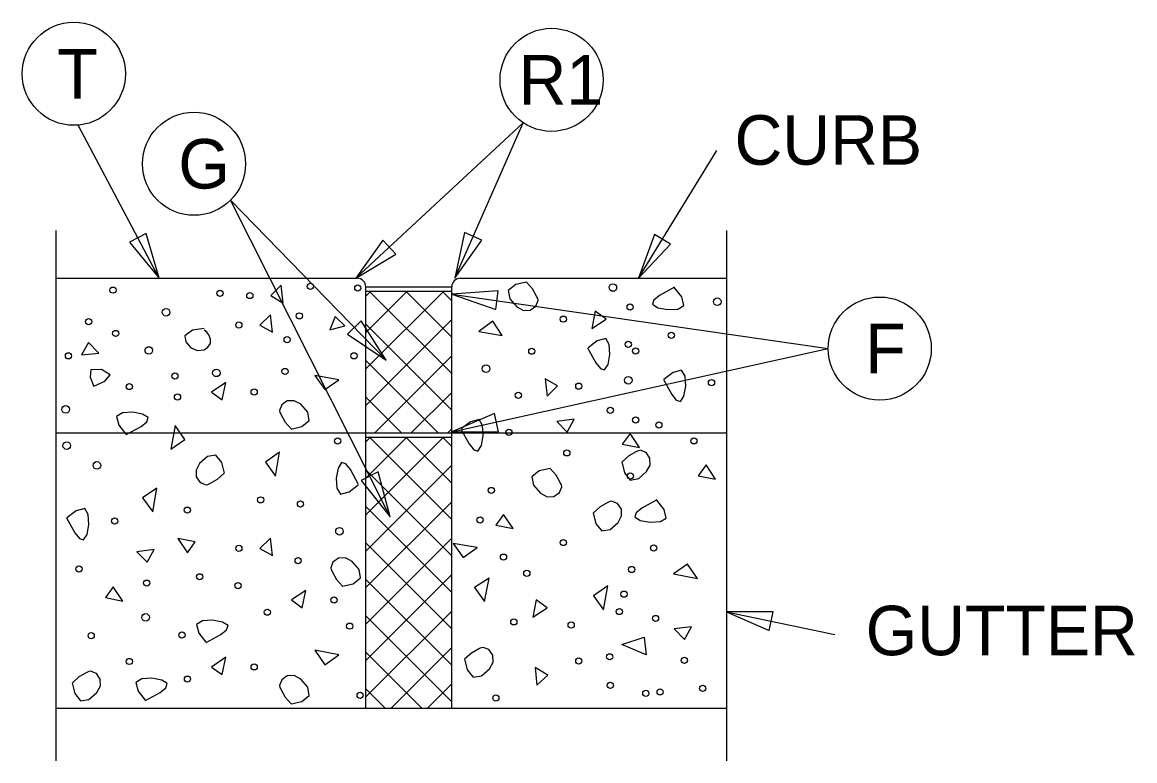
# Model space of a CAD drawing. Extents: x -439.1 to -407.9, y -458.1 to -436.2.
# Drawn here: x -431.656 to -428.285, y -452.451 to -450.213 of the extents above; entities that cross this region are included whole.
import ezdxf

# ---------------------------------------------------------------- set-up
doc = ezdxf.new("R2010")
doc.units = 0
doc.layers.add('Level 4', color=7, linetype='Continuous')

msp = doc.modelspace()

# ---------------------------------------------------------------- linework, layer by layer
at = {"layer": 'Level 4'}
for p, q in [((-431.2411, -450.9886), (-431.4866, -450.5246)), ((-430.645, -450.9886), (-430.1384, -450.5173)), ((-430.3448, -450.9886), (-430.1384, -450.5173)), ((-429.7884, -450.9886), (-429.5514, -450.6016)), ((-430.5533, -451.237), (-431.0251, -450.7522)), ((-430.5408, -451.7122), (-431.0251, -450.7522)), ((-431.5528, -452.4511), (-431.5528, -450.8438)), ((-429.5215, -452.4511), (-429.5215, -450.8438)), ((-431.5528, -450.9887), (-430.6415, -450.9887)), ((-430.329, -450.9887), (-429.5215, -450.9887)), ((-430.8715, -451.0099), (-430.9028, -451.0412)), ((-430.9028, -451.0412), (-430.8653, -451.0637)), ((-430.8653, -451.0637), (-430.8715, -451.0099)), ((-430.6153, -452.2912), (-430.6153, -451.0149)), ((-430.6153, -451.0149), (-430.354, -451.0149)), ((-430.6153, -451.0274), (-430.354, -451.0274)), ((-430.6149, -451.2635), (-430.3791, -451.0276)), ((-430.6149, -451.153), (-430.4896, -451.0276)), ((-430.6149, -451.0425), (-430.6, -451.0276)), ((-430.3545, -451.2778), (-430.6047, -451.0276)), ((-430.3545, -451.1673), (-430.4942, -451.0276)), ((-430.3545, -451.0569), (-430.3838, -451.0276)), ((-430.3545, -451.0369), (-429.2142, -451.2016)), ((-430.354, -452.2912), (-430.354, -451.0149)), ((-430.904, -451.0999), (-430.9365, -451.1312)), ((-430.8978, -451.1524), (-430.904, -451.0999)), ((-430.7078, -451.1049), (-430.724, -451.1449)), ((-430.679, -451.1324), (-430.7078, -451.1049)), ((-429.9203, -451.0887), (-429.9303, -451.1412)), ((-429.8865, -451.1124), (-429.9203, -451.0887)), ((-430.9365, -451.1312), (-430.8978, -451.1524)), ((-430.724, -451.1449), (-430.679, -451.1324)), ((-430.6149, -451.3739), (-430.3545, -451.1135)), ((-430.3545, -451.3883), (-430.6149, -451.1279)), ((-430.2303, -451.1187), (-430.2728, -451.1499)), ((-430.2015, -451.1624), (-430.2303, -451.1187)), ((-429.9303, -451.1412), (-429.8865, -451.1124)), ((-430.2728, -451.1499), (-430.2015, -451.1624)), ((-431.4553, -451.1837), (-431.4765, -451.2212)), ((-431.424, -451.2162), (-431.4553, -451.1837)), ((-430.3545, -451.4538), (-429.2142, -451.2016)), ((-431.4765, -451.2212), (-431.424, -451.2162)), ((-430.396, -451.4573), (-430.6149, -451.2384)), ((-430.5878, -451.4573), (-430.3545, -451.224)), ((-431.039, -451.3049), (-431.0828, -451.3337)), ((-431.0503, -451.3574), (-431.039, -451.3049)), ((-430.6965, -451.2962), (-430.769, -451.2837)), ((-430.769, -451.2837), (-430.739, -451.3262)), ((-430.739, -451.3262), (-430.6965, -451.2962)), ((-430.0715, -451.2937), (-430.0653, -451.3462)), ((-430.034, -451.3149), (-430.0715, -451.2937)), ((-431.0828, -451.3337), (-431.0503, -451.3574)), ((-430.4773, -451.4573), (-430.3545, -451.3345)), ((-430.0653, -451.3462), (-430.034, -451.3149)), ((-430.5065, -451.4573), (-430.6149, -451.3489)), ((-431.1928, -451.4349), (-431.2053, -451.5062)), ((-431.1628, -451.4774), (-431.1928, -451.4349)), ((-430.3668, -451.4573), (-430.3545, -451.445)), ((-429.984, -451.4162), (-430.0365, -451.4224)), ((-430.0365, -451.4224), (-430.0053, -451.4549)), ((-430.0053, -451.4549), (-429.984, -451.4162)), ((-431.5528, -451.4574), (-429.5215, -451.4574)), ((-431.2053, -451.5062), (-431.1628, -451.4774)), ((-430.6153, -451.4699), (-430.354, -451.4699)), ((-430.6149, -451.7054), (-430.3799, -451.4703)), ((-430.6149, -451.5949), (-430.4903, -451.4703)), ((-430.6149, -451.4844), (-430.6008, -451.4703)), ((-430.3545, -451.7198), (-430.604, -451.4703)), ((-430.3545, -451.6093), (-430.4935, -451.4703)), ((-430.3545, -451.4988), (-430.383, -451.4703)), ((-429.814, -451.4587), (-429.8378, -451.4912)), ((-429.7853, -451.5012), (-429.814, -451.4587)), ((-429.8378, -451.4912), (-429.7853, -451.5012)), ((-430.8765, -451.5162), (-430.919, -451.5462)), ((-430.919, -451.5462), (-430.889, -451.5887)), ((-430.889, -451.5887), (-430.8765, -451.5162)), ((-430.6149, -451.8159), (-430.3545, -451.5555)), ((-430.3545, -451.8302), (-430.6149, -451.5698)), ((-429.584, -451.5537), (-429.6078, -451.5874)), ((-429.5553, -451.5974), (-429.584, -451.5537)), ((-429.6078, -451.5874), (-429.5553, -451.5974)), ((-431.2478, -451.6249), (-431.2915, -451.6537)), ((-431.2603, -451.6962), (-431.2478, -451.6249)), ((-431.2915, -451.6537), (-431.2603, -451.6962)), ((-430.6149, -451.9263), (-430.3545, -451.6659)), ((-430.3545, -451.9407), (-430.6149, -451.6803)), ((-430.1978, -451.7049), (-430.2215, -451.7374)), ((-430.169, -451.7474), (-430.1978, -451.7049)), ((-430.2215, -451.7374), (-430.169, -451.7474)), ((-431.184, -451.7774), (-431.1553, -451.8212)), ((-431.1315, -451.7874), (-431.184, -451.7774)), ((-430.904, -451.7762), (-430.9365, -451.8074)), ((-430.8978, -451.8287), (-430.904, -451.7762)), ((-430.6149, -452.0368), (-430.3545, -451.7764)), ((-431.2565, -451.8112), (-431.309, -451.8174)), ((-431.2778, -451.8487), (-431.2565, -451.8112)), ((-431.1553, -451.8212), (-431.1315, -451.7874)), ((-430.9365, -451.8074), (-430.8978, -451.8287)), ((-430.3545, -452.0512), (-430.6149, -451.7908)), ((-430.2778, -451.8049), (-430.3503, -451.7924)), ((-430.3503, -451.7924), (-430.3203, -451.8349)), ((-430.3203, -451.8349), (-430.2778, -451.8049)), ((-431.309, -451.8174), (-431.2778, -451.8487)), ((-429.6403, -451.8549), (-429.6828, -451.8849)), ((-429.6103, -451.8987), (-429.6403, -451.8549)), ((-430.6149, -452.1473), (-430.3545, -451.8869)), ((-430.3545, -452.1617), (-430.6149, -451.9013)), ((-430.2415, -451.8974), (-430.2853, -451.9262)), ((-430.2553, -451.9687), (-430.2415, -451.8974)), ((-429.6828, -451.8849), (-429.6103, -451.8987)), ((-431.3803, -451.9237), (-431.404, -451.9562)), ((-431.3515, -451.9674), (-431.3803, -451.9237)), ((-430.7965, -451.9349), (-430.8403, -451.9637)), ((-430.8078, -451.9874), (-430.7965, -451.9349)), ((-430.2853, -451.9262), (-430.2553, -451.9687)), ((-429.8815, -451.9212), (-429.9253, -451.9512)), ((-429.9253, -451.9512), (-429.8953, -451.9937)), ((-429.8953, -451.9937), (-429.8815, -451.9212)), ((-431.404, -451.9562), (-431.3515, -451.9674)), ((-430.8403, -451.9637), (-430.8078, -451.9874)), ((-430.099, -451.9637), (-430.109, -452.0162)), ((-430.0653, -451.9874), (-430.099, -451.9637)), ((-430.6149, -452.2578), (-430.3545, -451.9974)), ((-430.3545, -452.2722), (-430.6149, -452.0118)), ((-430.109, -452.0162), (-430.0653, -451.9874)), ((-429.522, -451.9999), (-429.1939, -452.0688)), ((-429.6278, -452.0449), (-429.6803, -452.0512)), ((-429.6803, -452.0512), (-429.649, -452.0837)), ((-429.649, -452.0837), (-429.6278, -452.0449)), ((-429.839, -452.0987), (-429.7715, -452.0762)), ((-429.7715, -452.0762), (-429.7653, -452.1299)), ((-430.6965, -452.1299), (-430.769, -452.1162)), ((-430.769, -452.1162), (-430.739, -452.1599)), ((-430.5372, -452.2906), (-430.3545, -452.1079)), ((-429.7653, -452.1299), (-429.839, -452.0987)), ((-431.039, -452.1374), (-431.0828, -452.1674)), ((-431.0503, -452.1899), (-431.039, -452.1374)), ((-430.739, -452.1599), (-430.6965, -452.1299)), ((-430.4466, -452.2906), (-430.6149, -452.1222)), ((-431.0828, -452.1674), (-431.0503, -452.1899)), ((-430.1015, -452.1687), (-430.0965, -452.2224)), ((-430.064, -452.1912), (-430.1015, -452.1687)), ((-430.4268, -452.2906), (-430.3545, -452.2183)), ((-430.0965, -452.2224), (-430.064, -452.1912)), ((-430.557, -452.2906), (-430.6149, -452.2327)), ((-431.5528, -452.2912), (-429.5215, -452.2912))]:
    msp.add_line(p, q, dxfattribs=at)
for points in [[(-431.3312, -450.8797), (-431.2411, -450.9886), (-431.2804, -450.8529)], [(-430.3156, -450.8504), (-430.3448, -450.9886), (-430.263, -450.8734)], [(-429.7407, -450.8556), (-429.7884, -450.9886), (-429.6917, -450.8856)], [(-430.5633, -450.8733), (-430.645, -450.9886), (-430.5242, -450.9154)], [(-430.2136, -451.0265), (-430.3545, -451.0369), (-430.2212, -451.0835)], [(-430.6703, -451.1579), (-430.5533, -451.237), (-430.6292, -451.1178)], [(-430.2247, -451.3982), (-430.3545, -451.4538), (-430.2133, -451.4545)], [(-430.6287, -451.6017), (-430.5408, -451.7122), (-430.5774, -451.5758)], [(-429.3808, -452.0002), (-429.522, -451.9999), (-429.3926, -452.0564)]]:
    msp.add_lwpolyline(points, close=True, dxfattribs=at)
for points in [[(-430.128, -451.0003), (-430.1609, -451.008), (-430.1832, -451.026), (-430.1787, -451.0513), (-430.1575, -451.0756), (-430.1375, -451.0862), (-430.1167, -451.0856), (-430.0996, -451.0737), (-430.0928, -451.0561), (-430.0942, -451.0504), (-430.0966, -451.0448), (-430.1102, -451.021), (-430.128, -451.0009)], [(-429.68, -451.016), (-429.725, -451.041), (-429.7424, -451.0548), (-429.7465, -451.0674), (-429.7299, -451.0783), (-429.6997, -451.0837), (-429.6692, -451.0819), (-429.6511, -451.0712), (-429.658, -451.0451), (-429.6794, -451.0172)], [(-431.1045, -451.1405), (-431.1403, -451.1455), (-431.1635, -451.1631), (-431.1601, -451.1812), (-431.146, -451.1982), (-431.126, -451.2076), (-431.1052, -451.2058), (-431.0931, -451.198), (-431.0857, -451.1863), (-431.0855, -451.1729), (-431.0907, -451.16), (-431.0969, -451.1519), (-431.1045, -451.1455)], [(-429.9431, -451.1999), (-429.9181, -451.2449), (-429.9042, -451.2623), (-429.8916, -451.2665), (-429.8808, -451.2498), (-429.8754, -451.2197), (-429.8772, -451.1891), (-429.8879, -451.1711), (-429.914, -451.178), (-429.9418, -451.1993)], [(-431.4387, -451.3155), (-431.4056, -451.3005), (-431.3891, -451.2816), (-431.4155, -451.2648), (-431.4481, -451.2659), (-431.4499, -451.2888), (-431.4387, -451.3167)], [(-429.7133, -451.2958), (-429.6883, -451.3408), (-429.6744, -451.3582), (-429.6618, -451.3624), (-429.651, -451.3457), (-429.6456, -451.3156), (-429.6474, -451.285), (-429.6581, -451.267), (-429.6842, -451.2739), (-429.712, -451.2952)], [(-430.8415, -451.4456), (-430.8085, -451.4379), (-430.7862, -451.4199), (-430.7908, -451.3945), (-430.812, -451.3703), (-430.8319, -451.3597), (-430.8528, -451.3602), (-430.8698, -451.3721), (-430.8766, -451.3897), (-430.8753, -451.3954), (-430.8729, -451.401), (-430.8592, -451.4248), (-430.8415, -451.445)], [(-431.341, -451.4625), (-431.296, -451.4375), (-431.2787, -451.4237), (-431.2745, -451.4111), (-431.2911, -451.4002), (-431.3213, -451.3948), (-431.3519, -451.3966), (-431.3699, -451.4073), (-431.363, -451.4335), (-431.3416, -451.4613)], [(-430.3271, -451.446), (-430.3021, -451.491), (-430.2882, -451.5083), (-430.2756, -451.5125), (-430.2648, -451.4959), (-430.2594, -451.4657), (-430.2612, -451.4351), (-430.2719, -451.4171), (-430.298, -451.424), (-430.3258, -451.4454)], [(-429.8394, -451.5451), (-429.8317, -451.5781), (-429.8136, -451.6003), (-429.7883, -451.5958), (-429.7641, -451.5746), (-429.7534, -451.5547), (-429.754, -451.5338), (-429.7659, -451.5168), (-429.7835, -451.51), (-429.7892, -451.5113), (-429.7948, -451.5137), (-429.8186, -451.5273), (-429.8387, -451.5451)], [(-431.0433, -451.5797), (-431.051, -451.5467), (-431.069, -451.5245), (-431.0943, -451.529), (-431.1186, -451.5502), (-431.1292, -451.5701), (-431.1286, -451.591), (-431.1167, -451.608), (-431.0991, -451.6148), (-431.0934, -451.6135), (-431.0878, -451.6111), (-431.064, -451.5974), (-431.0439, -451.5797)], [(-430.6368, -451.6138), (-430.6618, -451.5688), (-430.6757, -451.5515), (-430.6883, -451.5473), (-430.6991, -451.5639), (-430.7045, -451.5941), (-430.7027, -451.6247), (-430.692, -451.6427), (-430.6659, -451.6358), (-430.6381, -451.6144)], [(-430.0564, -451.5649), (-430.0894, -451.5726), (-430.1116, -451.5906), (-430.1071, -451.6159), (-430.0859, -451.6402), (-430.066, -451.6508), (-430.0451, -451.6502), (-430.0281, -451.6383), (-430.0213, -451.6207), (-430.0226, -451.615), (-430.025, -451.6094), (-430.0387, -451.5856), (-430.0564, -451.5655)], [(-429.9262, -451.6995), (-429.9184, -451.7325), (-429.9004, -451.7547), (-429.8751, -451.7502), (-429.8509, -451.729), (-429.8402, -451.709), (-429.8408, -451.6882), (-429.8527, -451.6711), (-429.8703, -451.6643), (-429.876, -451.6657), (-429.8816, -451.6681), (-429.9054, -451.6817), (-429.9255, -451.6995)], [(-429.7334, -451.6604), (-429.7784, -451.6854), (-429.7958, -451.6992), (-429.7999, -451.7118), (-429.7833, -451.7227), (-429.7531, -451.7281), (-429.7225, -451.7263), (-429.7045, -451.7156), (-429.7115, -451.6895), (-429.7328, -451.6616)], [(-431.5217, -451.7151), (-431.4967, -451.7601), (-431.4828, -451.7775), (-431.4702, -451.7816), (-431.4594, -451.765), (-431.454, -451.7349), (-431.4558, -451.7043), (-431.4665, -451.6863), (-431.4926, -451.6932), (-431.5204, -451.7145)], [(-430.686, -451.9224), (-430.6531, -451.9147), (-430.6308, -451.8967), (-430.6353, -451.8714), (-430.6565, -451.8471), (-430.6765, -451.8365), (-430.6973, -451.8371), (-430.7144, -451.849), (-430.7212, -451.8666), (-430.7198, -451.8723), (-430.7174, -451.8779), (-430.7038, -451.9017), (-430.686, -451.9218)], [(-431.0989, -452.0931), (-431.054, -452.0681), (-431.0366, -452.0542), (-431.0324, -452.0416), (-431.0491, -452.0308), (-431.0792, -452.0254), (-431.1098, -452.0271), (-431.1278, -452.0378), (-431.1209, -452.064), (-431.0996, -452.0918)], [(-430.3155, -452.1426), (-430.3078, -452.1756), (-430.2897, -452.1978), (-430.2644, -452.1933), (-430.2402, -452.1721), (-430.2295, -452.1521), (-430.2301, -452.1313), (-430.242, -452.1142), (-430.2596, -452.1074), (-430.2653, -452.1088), (-430.2709, -452.1112), (-430.2947, -452.1248), (-430.3148, -452.1426)], [(-431.5047, -452.2147), (-431.497, -452.2476), (-431.479, -452.2699), (-431.4537, -452.2654), (-431.4294, -452.2442), (-431.4188, -452.2242), (-431.4194, -452.2034), (-431.4313, -452.1863), (-431.4489, -452.1795), (-431.4546, -452.1809), (-431.4602, -452.1833), (-431.484, -452.1969), (-431.5041, -452.2147)], [(-431.2829, -452.2688), (-431.2379, -452.2438), (-431.2205, -452.2299), (-431.2164, -452.2173), (-431.233, -452.2065), (-431.2632, -452.2011), (-431.2938, -452.2029), (-431.3118, -452.2136), (-431.3049, -452.2397), (-431.2835, -452.2675)], [(-430.8415, -452.2789), (-430.8085, -452.2712), (-430.7862, -452.2532), (-430.7908, -452.2278), (-430.812, -452.2036), (-430.8319, -452.193), (-430.8528, -452.1935), (-430.8698, -452.2054), (-430.8766, -452.223), (-430.8753, -452.2287), (-430.8729, -452.2343), (-430.8592, -452.2581), (-430.8415, -452.2783)]]:
    msp.add_lwpolyline(points, dxfattribs=at)
for centre, radius in [((-431.4996, -450.3689), 0.1562), ((-430.0521, -450.3872), 0.1562), ((-431.1355, -450.6417), 0.1562), ((-430.7832, -451.0134), 0.00937), ((-429.8665, -451.0167), 0.0115), ((-431.3809, -451.0247), 0.00937), ((-431.0565, -451.0346), 0.00937), ((-430.9664, -451.041), 0.00937), ((-430.6393, -451.0182), 0.00937), ((-429.8142, -451.0756), 0.00937), ((-429.5502, -451.0599), 0.0115), ((-429.0579, -451.2017), 0.1562), ((-431.2201, -451.0918), 0.0115), ((-430.8164, -451.1026), 0.00937), ((-430.0163, -451.1126), 0.00937), ((-431.4545, -451.1201), 0.00937), ((-430.9996, -451.1302), 0.00937), ((-431.3728, -451.156), 0.00937), ((-430.8533, -451.1749), 0.00937), ((-429.6894, -451.1616), 0.00937), ((-431.2724, -451.2075), 0.0115), ((-430.1121, -451.2098), 0.00937), ((-429.8197, -451.1889), 0.00937), ((-429.7975, -451.2093), 0.00937), ((-431.5159, -451.2238), 0.00937), ((-430.6506, -451.2238), 0.00937), ((-431.1934, -451.2847), 0.00937), ((-431.0676, -451.2754), 0.0115), ((-430.8599, -451.2712), 0.00937), ((-430.2505, -451.2627), 0.0115), ((-431.3316, -451.3169), 0.00937), ((-429.9698, -451.3157), 0.00937), ((-429.8197, -451.2979), 0.0115), ((-429.5677, -451.3052), 0.00937), ((-431.1855, -451.3483), 0.00937), ((-430.9532, -451.3333), 0.00937), ((-430.153, -451.3433), 0.00937), ((-431.5243, -451.386), 0.0115), ((-429.8743, -451.3892), 0.00937), ((-429.7974, -451.4184), 0.00937), ((-430.1815, -451.4554), 0.00937), ((-429.727, -451.4334), 0.00937), ((-430.7, -451.4821), 0.00937), ((-429.621, -451.4816), 0.00937), ((-431.5211, -451.4958), 0.0115), ((-430.0059, -451.5179), 0.00937), ((-431.4295, -451.556), 0.0115), ((-429.8138, -451.5878), 0.00937), ((-430.2348, -451.6318), 0.00937), ((-431.1556, -451.6914), 0.00937), ((-430.9336, -451.6603), 0.00937), ((-430.813, -451.6731), 0.00937), ((-431.3761, -451.7245), 0.00937), ((-430.2689, -451.7214), 0.00937), ((-430.6947, -451.7556), 0.0115), ((-430.0163, -451.7897), 0.00937), ((-430.9996, -451.8072), 0.00937), ((-429.7428, -451.806), 0.00937), ((-430.8201, -451.8449), 0.00937), ((-430.1978, -451.8338), 0.00937), ((-431.484, -451.8701), 0.00937), ((-431.1186, -451.8935), 0.00937), ((-430.1271, -451.883), 0.00937), ((-429.8096, -451.8714), 0.00937), ((-431.2787, -451.9127), 0.00937), ((-431.0021, -451.9206), 0.00937), ((-429.8327, -451.9462), 0.00937), ((-430.7111, -451.9638), 0.00937), ((-431.2822, -452.0165), 0.0115), ((-430.9132, -452.0008), 0.00937), ((-429.8467, -451.9989), 0.00937), ((-429.7372, -452.0198), 0.00937), ((-430.6641, -452.0431), 0.00937), ((-430.1665, -452.0302), 0.00937), ((-429.9928, -452.0394), 0.00937), ((-431.447, -452.0721), 0.00937), ((-431.1719, -452.0698), 0.00937), ((-431.3316, -452.1502), 0.00937), ((-429.9698, -452.149), 0.00937), ((-429.8759, -452.136), 0.00937), ((-429.6498, -452.1468), 0.00937), ((-430.9532, -452.1666), 0.00937), ((-431.1553, -452.2036), 0.00937), ((-429.8743, -452.2225), 0.00937), ((-430.6322, -452.2527), 0.00937), ((-430.221, -452.2608), 0.00937), ((-429.7667, -452.2469), 0.00937), ((-429.7234, -452.2423), 0.00937), ((-429.5944, -452.2318), 0.00937)]:
    msp.add_circle(centre, radius, dxfattribs=at)
for centre, start, end in [((-430.641, -451.0146), 0, 90), ((-430.3285, -451.0146), 90, 180)]:
    msp.add_arc(centre, 0.026, start, end, dxfattribs=at)

# ---------------------------------------------------------------- texts
for s, p in [('T', (-431.5496, -450.4439)), ('R1', (-430.1521, -450.4622)), ('CURB', (-429.4979, -450.6445)), ('G', (-431.183, -450.7167)), ('F', (-429.1017, -451.2766)), ('GUTTER', (-429.1006, -452.1313))]:
    msp.add_text(s, height=0.15, dxfattribs=at).set_placement(p)

doc.saveas('drawing.dxf')
